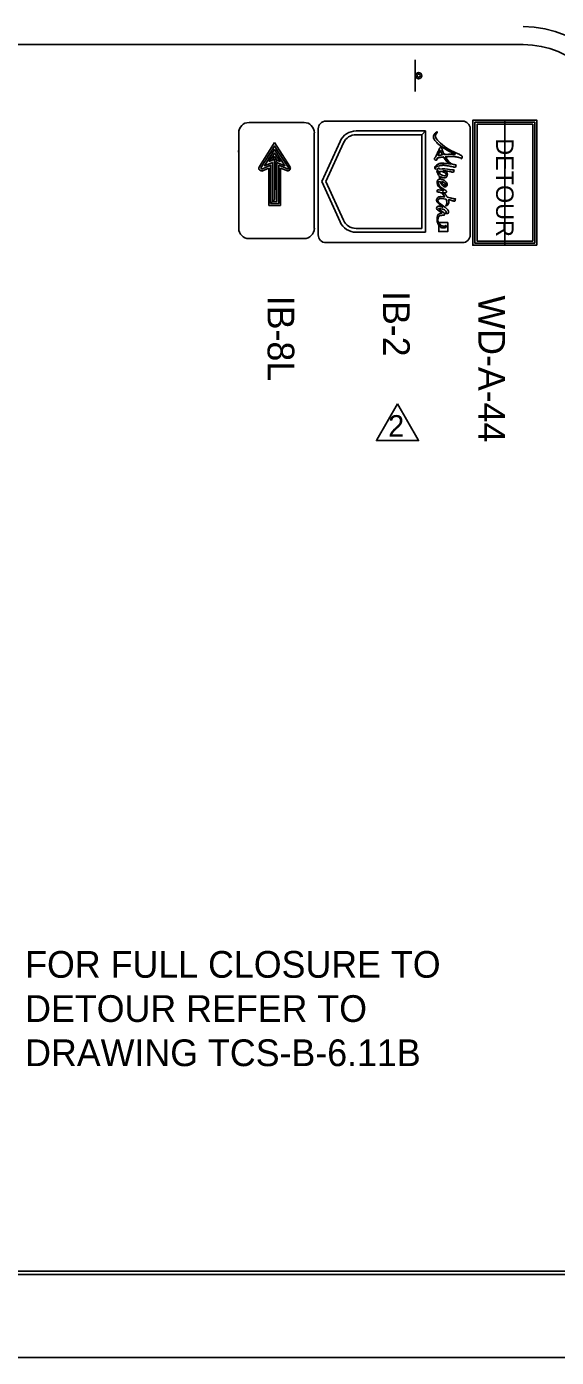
# Model space of a CAD drawing. Extents: x 1482 to 1692, y 225 to 494.
# Drawn here: x 1587.3 to 1622.9, y 224.6 to 314.2 of the extents above; entities that cross this region are included whole.
import ezdxf

# ---------------------------------------------------------------- set-up
doc = ezdxf.new("R2010")
doc.units = 0
for name, color, linetype in [('Level 17', 7, 'Continuous'), ('Level 2', 7, 'Continuous'), ('Level 53', 7, 'Continuous'), ('Level 60', 7, 'Continuous')]:
    doc.layers.add(name, color=color, linetype=linetype)

msp = doc.modelspace()

# ---------------------------------------------------------------- linework, layer by layer
at = {"layer": 'Level 17'}
for p, q in [((1613.423, 311.986), (1613.423, 309.853)), ((1602.254, 307.755), (1605.952, 307.755)), ((1619.462, 307.926), (1619.462, 299.488)), ((1601.556, 300.634), (1601.556, 307.071)), ((1601.904, 307.268), (1601.904, 307.268)), ((1602.947, 304.804), (1603.972, 306.417)), ((1603.972, 306.417), (1605.002, 304.804)), ((1606.637, 307.071), (1606.637, 300.634)), ((1603.576, 304.695), (1603.114, 304.497)), ((1603.576, 302.18), (1603.576, 304.689)), ((1604.836, 304.503), (1604.375, 304.695)), ((1604.375, 304.695), (1604.375, 302.18)), ((1604.375, 302.18), (1603.576, 302.18)), ((1605.952, 299.956), (1602.254, 299.956)), ((1617.349, 299.303), (1617.349, 299.303)), ((1617.349, 299.303), (1617.349, 299.303)), ((1617.349, 299.303), (1617.349, 299.303)), ((1617.349, 299.303), (1617.349, 299.303))]:
    msp.add_line(p, q, dxfattribs=at)
for points in [[(1621.616, 299.494), (1621.616, 307.92), (1617.308, 307.92), (1617.308, 299.494)], [(1621.474, 299.636), (1621.474, 307.78), (1617.448, 307.78), (1617.448, 299.636)], [(1621.335, 299.775), (1621.335, 307.64), (1617.59, 307.64), (1617.59, 299.775)]]:
    msp.add_lwpolyline(points, close=True, dxfattribs=at)
for points in [[(1601.55, 305.88), (1601.55, 305.772)], [(1603.697, 302.314), (1603.697, 304.887), (1603.102, 304.632), (1603.037, 304.701), (1603.972, 306.18), (1604.92, 304.695), (1604.88, 304.624), (1604.248, 304.887), (1604.248, 302.308), (1603.697, 302.314), (1603.83, 302.436), (1603.83, 305.079), (1603.28, 304.856), (1603.972, 305.937), (1604.663, 304.856), (1604.112, 305.079), (1604.112, 302.436), (1603.83, 302.436), (1603.96, 302.571), (1603.96, 305.29), (1603.613, 305.144), (1603.972, 305.7), (1604.336, 305.13), (1604.132, 305.214), (1603.972, 305.469), (1603.811, 305.226), (1603.978, 305.277), (1604.132, 305.214), (1604.042, 305.085), (1603.978, 302.577), (1603.96, 302.571)], [(1603.697, 302.314), (1603.697, 304.887)]]:
    msp.add_lwpolyline(points, dxfattribs=at)
for radius in [0.213, 0.107]:
    msp.add_circle((1613.662, 310.915), radius, dxfattribs=at)
for centre, radius, start, end in [((1602.248, 307.07), 0.692, 90, 180), ((1605.952, 307.07), 0.692, 0, 90), ((1603.112, 304.698), 0.199, 147.50378, 270.10575), ((1604.834, 304.701), 0.199, 270.10506, 32.49855), ((1602.248, 300.64), 0.692, 180, 270), ((1605.952, 300.64), 0.692, 270, 360)]:
    msp.add_arc(centre, radius, start, end, dxfattribs=at)
at = {"layer": 'Level 2'}
for p, q in [((1559.225, 313.009), (1620.696, 313.009)), ((1606.906, 307.336), (1606.906, 300.194)), ((1616.611, 307.854), (1607.424, 307.854)), ((1617.129, 307.336), (1617.129, 300.194)), ((1617.129, 307.336), (1617.129, 300.194)), ((1607.139, 303.786), (1608.371, 306.495)), ((1608.604, 306.389), (1607.42, 303.786)), ((1609.457, 307.194), (1614.125, 307.194)), ((1613.869, 306.938), (1609.457, 306.938)), ((1614.125, 307.194), (1613.869, 306.938)), ((1613.869, 306.938), (1614.125, 307.194)), ((1613.869, 300.634), (1613.869, 306.938)), ((1614.125, 307.194), (1614.125, 300.378)), ((1608.371, 301.077), (1607.139, 303.786)), ((1607.42, 303.786), (1608.604, 301.183)), ((1609.457, 300.634), (1613.869, 300.634)), ((1614.125, 300.378), (1609.457, 300.378)), ((1616.611, 299.676), (1607.424, 299.676))]:
    msp.add_line(p, q, dxfattribs=at)
for centre, radius, start, end in [((1620.697, 306.96), 7.258, 0, 90), ((1620.697, 306.96), 6.048, 0, 90), ((1607.424, 307.336), 0.518, 90, 180), ((1616.611, 307.336), 0.518, 360, 90), ((1609.457, 306.001), 1.193, 90, 155.54318), ((1609.457, 306.001), 0.937, 90, 155.54318), ((1609.457, 301.571), 1.193, 204.45682, 270), ((1609.457, 301.571), 0.937, 204.45682, 270), ((1607.424, 300.194), 0.518, 180, 270), ((1616.611, 300.194), 0.518, 270, 360)]:
    msp.add_arc(centre, radius, start, end, dxfattribs=at)
at = {"layer": 'Level 53'}
msp.add_line((1615.014, 300.856), (1615.014, 301.006), dxfattribs=at)
msp.add_lwpolyline([(1615.014, 300.856), (1615.014, 300.416), (1615.622, 300.416), (1615.622, 301.024), (1615.014, 301.024), (1615.014, 301.006)], dxfattribs=at)
for points, degree in [([(1614.793, 304.669), (1614.803, 304.734), (1614.892, 304.82), (1615.038, 304.846), (1615.301, 304.892), (1615.561, 304.865), (1615.949, 304.787), (1616.022, 304.773), (1616.149, 304.723), (1616.174, 304.882), (1616.181, 304.932), (1616.156, 304.906), (1616.089, 304.92), (1615.801, 304.981), (1615.593, 305.217), (1615.454, 305.454), (1615.784, 305.479), (1616.151, 305.469), (1616.376, 305.407), (1616.565, 305.354), (1616.531, 305.292), (1616.57, 305.369), (1616.613, 305.451), (1616.557, 305.538), (1616.416, 305.609), (1616.274, 305.68), (1615.507, 306.006), (1614.988, 306.527), (1614.723, 306.794), (1614.86, 307.035), (1614.901, 307.083), (1614.934, 307.123), (1614.883, 307.137), (1614.83, 307.088), (1614.598, 306.873), (1614.731, 306.558), (1614.846, 306.443), (1615.163, 306.126), (1615.845, 305.757), (1616.134, 305.608), (1615.971, 305.622), (1615.698, 305.627), (1615.378, 305.596), (1615.299, 305.758), (1615.253, 305.902), (1615.235, 305.97), (1615.215, 306.044), (1615.185, 306.09), (1615.151, 306.091), (1615.114, 306.093), (1615.082, 306.043), (1615.048, 305.972), (1614.987, 305.844), (1614.811, 305.47), (1614.757, 305.378), (1614.711, 305.299), (1614.747, 305.26), (1614.796, 305.237), (1614.861, 305.206), (1614.898, 305.29), (1614.922, 305.371), (1615.031, 305.402), (1615.177, 305.427), (1615.337, 305.444), (1615.454, 305.254), (1615.61, 305.067), (1615.805, 304.959), (1615.642, 304.986), (1615.089, 305.056), (1614.855, 304.881), (1614.803, 304.842), (1614.747, 304.757), (1614.755, 304.674), (1614.759, 304.635), (1614.785, 304.616), (1614.793, 304.62), (1614.801, 304.623), (1614.789, 304.646), (1614.793, 304.669)], 3), ([(1615.454, 305.454), (1615.784, 305.479), (1616.151, 305.469), (1616.376, 305.407), (1616.565, 305.354), (1616.531, 305.292), (1616.57, 305.369), (1616.613, 305.451), (1616.557, 305.538), (1616.416, 305.609), (1616.274, 305.68), (1615.507, 306.006), (1614.988, 306.527), (1614.723, 306.794), (1614.86, 307.035), (1614.901, 307.083), (1614.934, 307.123), (1614.883, 307.137), (1614.83, 307.088), (1614.598, 306.873), (1614.731, 306.558), (1614.846, 306.443), (1615.163, 306.126), (1615.845, 305.757), (1616.134, 305.608)], 3), ([(1615.378, 305.596), (1615.299, 305.758), (1615.253, 305.902), (1615.235, 305.97), (1615.215, 306.044), (1615.185, 306.09), (1615.151, 306.091), (1615.114, 306.093), (1615.082, 306.043), (1615.048, 305.972), (1614.987, 305.844), (1614.811, 305.47), (1614.757, 305.378), (1614.711, 305.299), (1614.747, 305.26), (1614.796, 305.237), (1614.861, 305.206), (1614.898, 305.29), (1614.922, 305.371)], 3), ([(1614.967, 305.533), (1614.997, 305.616), (1615.045, 305.734), (1615.123, 305.888)], 2), ([(1615.258, 305.584), (1615.129, 305.568), (1615.036, 305.552), (1614.967, 305.533)], 2), ([(1615.123, 305.888), (1615.154, 305.804), (1615.199, 305.697), (1615.258, 305.584), (1615.129, 305.568), (1615.036, 305.552), (1614.967, 305.533), (1614.997, 305.616), (1615.045, 305.734), (1615.123, 305.888)], 3), ([(1615.123, 305.888), (1615.154, 305.804), (1615.199, 305.697), (1615.258, 305.584)], 2), ([(1616.134, 305.608), (1615.971, 305.622), (1615.698, 305.627), (1615.378, 305.596)], 2), ([(1615.805, 304.959), (1615.642, 304.986), (1615.089, 305.056), (1614.855, 304.881), (1614.803, 304.842), (1614.747, 304.757), (1614.755, 304.674), (1614.759, 304.635), (1614.785, 304.616), (1614.793, 304.62), (1614.801, 304.623), (1614.789, 304.646), (1614.793, 304.669)], 3), ([(1614.793, 304.669), (1614.803, 304.734), (1614.892, 304.82), (1615.038, 304.846), (1615.301, 304.892), (1615.561, 304.865), (1615.949, 304.787), (1616.022, 304.773), (1616.149, 304.723), (1616.174, 304.882), (1616.181, 304.932), (1616.156, 304.906), (1616.089, 304.92), (1615.801, 304.981), (1615.593, 305.217), (1615.454, 305.454)], 3), ([(1615.062, 304.626), (1615.04, 304.694), (1614.989, 304.722), (1614.935, 304.634), (1614.897, 304.573), (1614.885, 304.44), (1614.951, 304.305), (1614.975, 304.257), (1615.009, 304.215), (1615.048, 304.18)], 3), ([(1614.922, 305.371), (1615.031, 305.402), (1615.177, 305.427), (1615.337, 305.444)], 2), ([(1615.295, 304.522), (1615.45, 304.51), (1615.639, 304.485), (1615.814, 304.45), (1615.887, 304.435), (1616.014, 304.385), (1616.039, 304.544), (1616.047, 304.595), (1616.023, 304.587), (1615.955, 304.583), (1615.863, 304.577), (1615.307, 304.679), (1615.062, 304.626)], 3), ([(1615.337, 305.444), (1615.454, 305.254), (1615.61, 305.067), (1615.805, 304.959)], 2), ([(1615.087, 303.938), (1614.98, 303.925), (1614.898, 303.855), (1614.913, 303.692), (1614.934, 303.462), (1615.218, 303.257), (1615.354, 303.18)], 3), ([(1614.962, 304.447), (1614.959, 304.469), (1614.959, 304.487), (1614.962, 304.502)], 2), ([(1614.962, 304.502), (1614.969, 304.493), (1614.98, 304.488), (1614.993, 304.488), (1615.001, 304.488), (1615.01, 304.488), (1615.019, 304.487)], 3), ([(1615.031, 304.335), (1614.994, 304.369), (1614.968, 304.407), (1614.962, 304.447)], 2), ([(1615.234, 303.067), (1615.309, 303.052), (1615.393, 303.028), (1615.449, 303.027), (1615.508, 303.025), (1615.521, 303.065), (1615.526, 303.081), (1615.536, 303.116), (1615.519, 303.157), (1615.461, 303.198), (1615.325, 303.295), (1615.11, 303.417), (1615.02, 303.602), (1614.956, 303.735), (1615.021, 303.793), (1615.121, 303.796)], 3), ([(1615.019, 304.487), (1615.021, 304.453), (1615.024, 304.399), (1615.031, 304.335)], 2), ([(1615.048, 304.18), (1615.058, 304.099), (1615.071, 304.015), (1615.087, 303.938)], 2), ([(1615.097, 304.287), (1615.09, 304.348), (1615.085, 304.413), (1615.079, 304.481)], 2), ([(1615.079, 304.481), (1615.275, 304.456), (1615.546, 304.354), (1615.502, 304.228), (1615.477, 304.155), (1615.249, 304.193), (1615.097, 304.287)], 3), ([(1615.115, 304.13), (1615.298, 304.017), (1615.546, 304.027), (1615.588, 304.192), (1615.636, 304.384), (1615.45, 304.481), (1615.295, 304.522)], 3), ([(1615.147, 303.94), (1615.135, 303.995), (1615.124, 304.059), (1615.115, 304.13)], 2), ([(1615.121, 303.796), (1615.129, 303.77), (1615.137, 303.747), (1615.146, 303.727), (1615.253, 303.486), (1615.414, 303.403), (1615.511, 303.464), (1615.605, 303.522), (1615.576, 303.688), (1615.438, 303.82), (1615.37, 303.884), (1615.253, 303.934), (1615.147, 303.94)], 3), ([(1615.426, 303.668), (1615.501, 303.587), (1615.496, 303.547), (1615.475, 303.536), (1615.432, 303.513), (1615.278, 303.608), (1615.194, 303.79)], 3), ([(1615.194, 303.79), (1615.277, 303.774), (1615.367, 303.731), (1615.426, 303.668)], 2), ([(1615.354, 303.18), (1615.208, 303.194), (1614.888, 303.289), (1614.904, 303.126), (1614.911, 303.063), (1614.921, 303.09), (1614.976, 303.086), (1615.169, 303.072), (1615.332, 302.912), (1615.432, 302.753)], 3), ([(1615.596, 302.73), (1615.522, 302.859), (1615.397, 302.979), (1615.234, 303.067)], 2), ([(1615.432, 302.753), (1615.196, 302.781), (1614.985, 302.771), (1614.919, 302.664), (1614.795, 302.468), (1615.12, 302.189), (1615.318, 302.035)], 3), ([(1615.318, 302.035), (1615.142, 302.114), (1614.916, 302.158), (1614.882, 302.04), (1614.842, 301.903), (1615.07, 301.794), (1615.245, 301.667)], 3), ([(1614.96, 301.194), (1614.96, 301.444), (1615.153, 301.508), (1615.25, 301.52), (1615.313, 301.528), (1615.406, 301.514), (1615.393, 301.625), (1615.385, 301.702), (1615.235, 301.772), (1615.108, 301.869), (1614.999, 301.953), (1615.01, 301.991), (1615.103, 301.971), (1615.22, 301.947), (1615.494, 301.85), (1615.514, 301.738), (1615.523, 301.686), (1615.432, 301.668), (1615.489, 301.644), (1615.546, 301.621), (1615.669, 301.642), (1615.669, 301.758), (1615.669, 301.839), (1615.583, 301.936), (1615.485, 302.015), (1615.4, 302.084), (1614.885, 302.435), (1614.996, 302.582), (1615.048, 302.65), (1615.26, 302.645), (1615.51, 302.602)], 3), ([(1615.51, 302.602), (1615.577, 302.427), (1615.555, 302.282), (1615.515, 302.2), (1615.496, 302.16), (1615.499, 302.154), (1615.543, 302.171), (1615.609, 302.197), (1615.711, 302.337), (1615.664, 302.556), (1615.663, 302.562), (1615.662, 302.567), (1615.66, 302.572)], 3), ([(1615.66, 302.572), (1615.742, 302.554), (1615.824, 302.534), (1615.904, 302.511), (1615.977, 302.491), (1616.104, 302.431), (1616.129, 302.588), (1616.137, 302.638), (1616.112, 302.617), (1616.045, 302.633), (1615.92, 302.664), (1615.758, 302.702), (1615.596, 302.73)], 3), ([(1615.245, 301.667), (1615.119, 301.653), (1614.903, 301.569), (1614.903, 301.232), (1614.903, 301.08), (1614.946, 300.952), (1615.014, 300.856)], 3), ([(1615.014, 301.006), (1614.98, 301.062), (1614.96, 301.126), (1614.96, 301.194)], 2), ([(1615.622, 301.024), (1615.622, 301.024), (1615.014, 301.024), (1615.014, 301.024), (1615.014, 301.024), (1615.014, 301.006), (1615.014, 301.006), (1615.093, 300.874), (1615.244, 300.785), (1615.368, 300.786), (1615.475, 300.786), (1615.47, 300.843), (1615.485, 300.836), (1615.528, 300.818), (1615.503, 300.683), (1615.352, 300.676), (1615.223, 300.669), (1615.099, 300.736), (1615.014, 300.856), (1615.014, 300.856), (1615.014, 300.416), (1615.014, 300.416), (1615.014, 300.416), (1615.622, 300.416), (1615.622, 300.416), (1615.622, 300.416), (1615.622, 301.024), (1615.622, 301.024)], 3), ([(1615.014, 301.006), (1615.093, 300.874), (1615.244, 300.785), (1615.368, 300.786), (1615.475, 300.786), (1615.47, 300.843), (1615.485, 300.836), (1615.528, 300.818), (1615.503, 300.683), (1615.352, 300.676), (1615.223, 300.669), (1615.099, 300.736), (1615.014, 300.856)], 3)]:
    msp.add_open_spline(points, degree=degree, dxfattribs=at)
at = {"layer": 'Level 60'}
for points in [[(1482.41, 493.623), (1692.41, 493.623), (1692.41, 224.631), (1482.41, 224.631)], [(1493.127, 487.958), (1687.519, 487.958), (1687.519, 230.208), (1493.127, 230.208)], [(1500.536, 487.818), (1687.41, 487.818), (1687.41, 230.436), (1500.536, 230.436)]]:
    msp.add_lwpolyline(points, close=True, dxfattribs=at)
for points in [[(1612.24, 288.815), (1610.847, 286.39)], [(1613.634, 286.39), (1612.24, 288.815)], [(1610.847, 286.39), (1610.821, 286.345), (1613.66, 286.345), (1613.634, 286.39)]]:
    msp.add_lwpolyline(points, dxfattribs=at)

# ---------------------------------------------------------------- texts
at = {"layer": 'Level 17'}
for s, height, rotation, p in [('DETOUR', 1.1758, 270, (1618.874, 306.699)), ('IB-8L', 1.8, 269.99999, (1603.497, 296.1)), ('IB-2', 1.8, 269.99999, (1611.264, 296.417)), ('WD-A-44', 1.8, 269.99999, (1617.682, 296.122))]:
    msp.add_text(s, height=height, rotation=rotation, dxfattribs=at).set_placement(p)
for s, p in [('FOR FULL CLOSURE TO ', (1587.188, 250.188)), ('DETOUR REFER TO ', (1587.188, 247.213)), ('DRAWING TCS-B-6.11B', (1587.188, 244.238))]:
    msp.add_text(s, height=1.8, dxfattribs=at).set_placement(p)
at = {"layer": 'Level 60'}
msp.add_text('2', height=1.448, rotation=360, dxfattribs=at).set_placement((1611.613, 286.614))

doc.saveas('drawing.dxf')
